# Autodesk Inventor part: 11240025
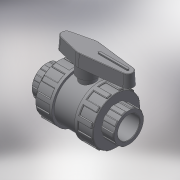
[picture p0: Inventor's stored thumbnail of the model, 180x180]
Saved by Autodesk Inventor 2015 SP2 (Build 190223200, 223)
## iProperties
Created: 2017-11
Part Number: 11240025
Material: Generic
Description: PLASSON BI STOP VALVE CEM PVC 25
Document SubType Name: Modeling
Designer: KIM
Density: 1 g/cm^3
Appearance: Default
Author: KIM
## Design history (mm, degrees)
derived "112400 - 112700.ipt"
feature "Solid1::112400 - 112700.ipt"
tag "TaggingFeature1"
body "Solid1"
other parameters: "d0" = 89, "d1" = 25, "d2" = 55, "d3" = 19, "d5" = 13.3, "d7" = 35, "d8" = 49.5, "d13" = 0.75, "d23" = 19, "d24" = 52.8, "d25" = 0.5, "d26" = 0.75, "d27" = 8.25, "d28" = 4.125, "d29" = 14.25, "d30" = 0, "d35" = 0.75, "d39" = 27.5, "d45" = 360 deg, "d47" = 0.5, "d50" = 30.25, "d51" = 16.5, "d53" = 0, "d55" = 5, "d56" = 2.5, "d57" = 13.3, "d58" = 0, "d59" = 0.75, "d61" = 360 deg, "d63" = 22, "d64" = 54, "d66" = 73, "d68" = 11, "d69" = 21.9, "d70" = 13.5, "d71" = 3 deg, "d73" = 1.1, "d74" = 29.2, "d75" = 1.62, "d76" = 0, "d77" = 0.5, "d_" = 25, "l_" = 19, "H_" = 89, "K_" = 55, "F_" = 54, "J_" = 73, "d67" = 22, "d72" = 5.5
